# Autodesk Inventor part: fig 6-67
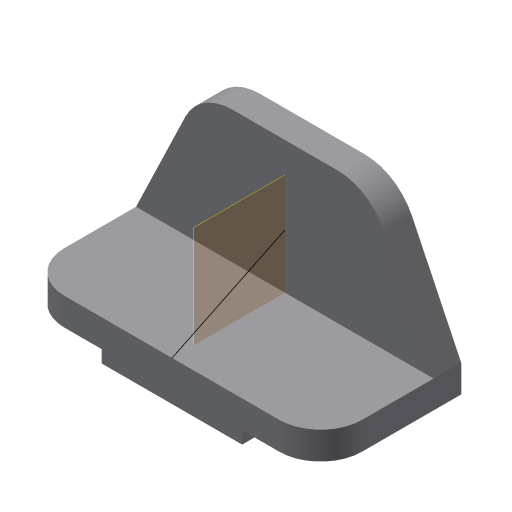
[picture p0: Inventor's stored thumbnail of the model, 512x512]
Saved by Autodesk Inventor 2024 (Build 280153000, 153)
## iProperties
Shininess: 77.0
Length Units: 11269
Angle Units: 11279
Time Units: 11290
Mass Units: 11283
Length Display Precision: 3
Angle Display Precision: 2
Created: 2001-12
Part Number: fig 6-67
Document SubType Name: Modeling
Designer: Renu Muthoo
Density: 1 g/cm^3
Material: Generic
Appearance: Default
Density: 0.0
Volumn: 0.0
Area: 0.0
PropertySet Name: Model Information
Control State: 0
Master: False
Checked Out: False
Author: Renu Muthoo
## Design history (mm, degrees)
sketch "Sketch2"
  geometry: L1 (-67.219, 19.116)-(148.781, 19.116); L2 (148.781, 19.116)-(148.781, -0.884); L3 (-67.219, -0.884)-(-67.219, 19.116); L4 (-10.219, -0.884)-(-10.219, -9.884); L5 (-10.219, -9.884)-(91.781, -9.884); L6 (91.781, -9.884)-(91.781, -0.884); L7 (148.781, -0.884)-(91.781, -0.884); L8 (-10.219, -0.884)-(-67.219, -0.884)
  constraints: 16 end point, 5 parallel, 4 perpendicular, 2 equal length, 1 horizontal
  dimensions: "d0" = 102 distance of L4.end L5.end; "d1" = 57 distance of L4.start L3.start; "d2" = 29 distance between parallel lines of L1 L5; "d3" = 20 distance of L1.end L2.end
extrude "Extrusion1" new body sketch "Sketch2" distance "d4" = 102; taper "d5" = 0 deg
sketch "Sketch3"
  geometry: L1 (67.219, -19.116)-(-148.781, -19.116) reference; L2 (67.219, -19.116)-(31.475, -93.564); L3 (-2.781, -115.116)-(-78.781, -115.116); L4 (-113.038, -93.564)-(-148.781, -19.116); A1 r 38 centre (-2.781, -77.116) between (-2.781, -115.116) and (31.475, -93.564); A2 r 38 centre (-78.781, -77.116) between (-113.038, -93.564) and (-78.781, -115.116)
  constraints: 6 end point, 4 point on circle, 4 tangent, 2 centre point, 1 equal length, 1 equal radius, 1 parallel
  dimensions: "d6" = 96 distance between parallel lines of L3 L1; "d7" = 38 radius of A1; "d8" = 76 distance of A2.centre A1.centre
extrude "Extrusion2" join sketch "Sketch3" distance "d9" = 20; taper "d10" = 0 deg
fillet "Fillet1" dims "d11" = 30
workplane "Work Plane1"
sketch "Sketch7"
  geometry: L1 (0, -82)-(-39.557, 0)
  constraints: 2 end point
body "Solid1"
node "Sketch1"
other parameters: "d12" = -108
